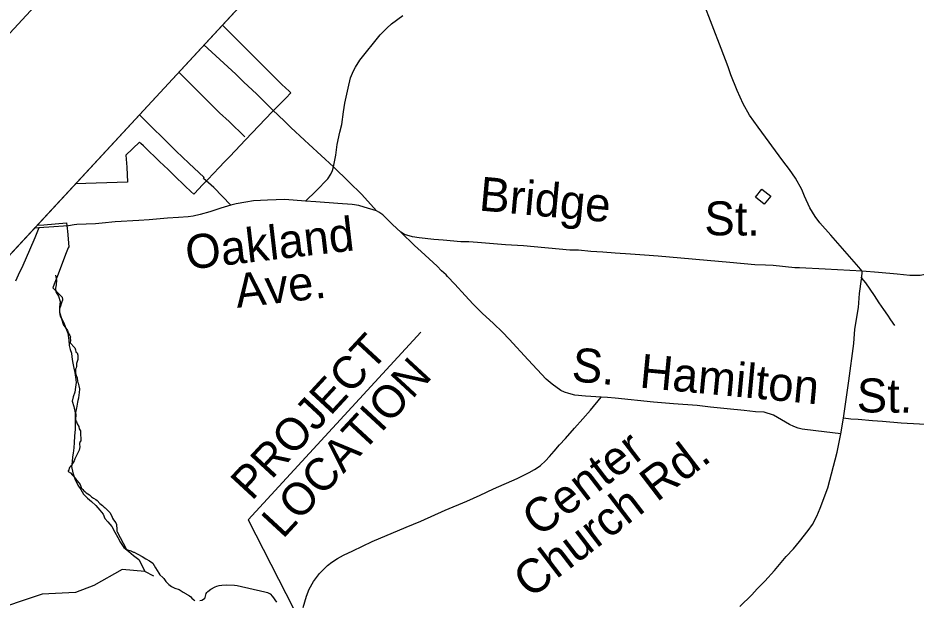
# Model space of a CAD drawing. Extents: x 1766669 to 1770980, y 998119 to 1002502.
# Drawn here: x 1767070.6 to 1767473.1, y 999839.2 to 1000100.2 of the extents above; entities that cross this region are included whole.
import ezdxf

# ---------------------------------------------------------------- set-up
doc = ezdxf.new("R2010")
doc.units = 0
for name, color, linetype in [('CTL Vertical Benchmark CELL', 7, 'Continuous'), ('Default', 7, 'Continuous'), ('Default Symbol CELL', 7, 'Continuous'), ('Exist DTM Breakline', 7, 'Continuous'), ('Exist DTM Breakline Underwater', 7, 'Continuous'), ('Exist Hydro Stream or Body of Water', 7, 'Continuous'), ('Exist Roads EOP', 7, 'Continuous'), ('Exist Structure Minor Pipes RCP 15 Inch', 7, 'Continuous'), ('Exist Structure Minor Pipes RCP 24 Inch', 7, 'Continuous')]:
    doc.layers.add(name, color=color, linetype=linetype)

msp = doc.modelspace()

# ---------------------------------------------------------------- linework, layer by layer
at = {"layer": 'CTL Vertical Benchmark CELL'}
for points in [[(1767448.78, 999983.55), (1767448.72, 999983.61), (1767448.45, 999983.95)], [(1767463.59, 999962.32), (1767461.83, 999964.83), (1767460.52, 999966.94), (1767458.7, 999969.51), (1767456.63, 999972.45), (1767454.43, 999975.75), (1767450.65, 999981.4), (1767448.78, 999983.55)]]:
    msp.add_lwpolyline(points, dxfattribs=at)
at = {"layer": 'Default'}
msp.add_lwpolyline([(1766911.45, 999825.82), (1767342.39, 1000292.03), (1767769.56, 999897.17), (1767338.62, 999430.96)], close=True, dxfattribs=at)
at = {"layer": 'Default Symbol CELL'}
for p, q in [((1769180.49, 1002379.93), (1766847.82, 999856.35)), ((1766911.45, 999825.82), (1767342.36, 1000292.01))]:
    msp.add_line(p, q, dxfattribs=at)
msp.add_lwpolyline([(1767251.23, 999959.27), (1767173.81, 999875.14), (1767194.02, 999835.43)], dxfattribs=at)
at = {"layer": 'Exist DTM Breakline'}
for p, q in [((1767079.99, 1000006.03), (1767077.93, 1000005.93)), ((1767448.78, 999983.55), (1767449.03, 999986.62)), ((1767439.43, 999913.72), (1767440.57, 999920.8))]:
    msp.add_line(p, q, dxfattribs=at)
for points in [[(1767449.03, 999986.62), (1767447.48, 999988.44), (1767434.84, 1000002.74), (1767430.04, 1000008.32), (1767427.83, 1000011.11), (1767425.5, 1000015.03), (1767423.11, 1000020.29), (1767421.99, 1000023.33), (1767419.11, 1000028.33), (1767416.37, 1000032.2), (1767413.4, 1000036.07), (1767402.41, 1000051.25), (1767398.48, 1000056.64), (1767395.65, 1000061.67), (1767392.91, 1000067.67), (1767390.15, 1000074.65), (1767388.94, 1000078.28), (1767385.7, 1000086.52), (1767377.73, 1000107.42)], [(1767212.01, 1000033.41), (1767213.09, 1000038.6), (1767213.69, 1000043.42), (1767214.89, 1000048.94), (1767215.69, 1000052.39), (1767216.47, 1000058.04), (1767217.14, 1000061.91), (1767218.53, 1000068.78), (1767219.69, 1000073.3), (1767221.05, 1000076.42), (1767221.91, 1000078.19), (1767223.75, 1000081.3), (1767232.93, 1000092.59), (1767235.92, 1000095.68), (1767237.94, 1000097.55), (1767243.03, 1000101.29)], [(1767212.01, 1000033.41), (1767200.97, 1000043.63), (1767198.95, 1000045.39), (1767192.95, 1000051.12), (1767190.11, 1000053.85), (1767184.62, 1000059.05), (1767184.5, 1000059.17), (1767177.49, 1000066.13), (1767171.81, 1000071.4), (1767168.2, 1000074.98), (1767153.97, 1000088.19)], [(1767142.63, 1000075.92), (1767160.93, 1000057.67), (1767165.28, 1000053.74), (1767172.35, 1000046.96)], [(1767166.06, 1000016.3), (1767158.42, 1000024.13), (1767153.74, 1000028.21), (1767154.13, 1000028.64), (1767147.13, 1000035.02), (1767141.46, 1000040.48), (1767124.98, 1000056.83)], [(1767199.51, 1000018.05), (1767204.24, 1000022.72), (1767209.44, 1000028.04), (1767210.86, 1000030.15), (1767211.53, 1000031.74), (1767212.01, 1000033.41)], [(1767231.36, 1000013.67), (1767224.71, 1000021.01), (1767218.84, 1000026.7), (1767212.01, 1000033.41)], [(1767199.51, 1000018.05), (1767190.2, 1000018.74), (1767182.41, 1000018.56), (1767176.24, 1000018.12), (1767172.72, 1000017.54), (1767168.46, 1000016.87), (1767166.06, 1000016.3)], [(1767166.06, 1000016.3), (1767161.5, 1000014.85), (1767156.53, 1000013.21), (1767152.23, 1000012.1), (1767149.07, 1000011.37), (1767146.89, 1000010.99), (1767142.56, 1000010.77), (1767137.59, 1000010.38), (1767129.43, 1000009.66), (1767124.75, 1000009.38), (1767114.15, 1000008.79), (1767108.27, 1000008.14), (1767105.36, 1000007.92), (1767096.94, 1000007.54), (1767095.75, 1000007.4), (1767093.22, 1000007.05), (1767084.51, 1000006.46), (1767079.99, 1000006.03)], [(1767231.36, 1000013.67), (1767225.82, 1000015.41), (1767223.36, 1000016.04), (1767220.42, 1000016.54), (1767213.95, 1000017.04), (1767204.06, 1000017.7), (1767199.51, 1000018.05)], [(1767242.19, 1000004.21), (1767240.36, 1000005.79), (1767238.34, 1000007.78), (1767234.06, 1000011.86), (1767232.37, 1000013.13), (1767231.36, 1000013.67)], [(1767079.99, 1000006.03), (1767078.17, 1000001.67), (1767075.75, 999996.04), (1767072.73, 999989.14), (1767070.65, 999984.82), (1767069.43, 999982.14)], [(1767449.03, 999986.62), (1767432.41, 999987.56), (1767420.86, 999988.17), (1767418.73, 999988.17), (1767409, 999989.16), (1767405.57, 999989.41), (1767400.85, 999989.49), (1767389.65, 999990.51), (1767357.6, 999993.38), (1767351.4, 999993.87), (1767345.1, 999994.26), (1767338.28, 999994.72), (1767332.71, 999995.24), (1767327.35, 999995.55), (1767321.78, 999996.07), (1767317.91, 999996.02), (1767297.2, 999998.04), (1767289.12, 999998.46), (1767276.51, 999999.44), (1767272.62, 999999.81), (1767269.06, 999999.88), (1767261.19, 1000000.53), (1767256.99, 1000000.8), (1767250.39, 1000001.64), (1767247.4, 1000002.07), (1767243.81, 1000003.17), (1767242.19, 1000004.21)], [(1767331.92, 999930.19), (1767325.01, 999930.56), (1767320.23, 999931.11), (1767317.47, 999931.85), (1767315.49, 999932.37), (1767313.9, 999933.2), (1767310.02, 999935.99), (1767307.32, 999938.3), (1767299.33, 999946.87), (1767290.79, 999956.2), (1767287.77, 999959.34), (1767283.73, 999963.17), (1767278.66, 999967.86), (1767274.56, 999971.89), (1767271.03, 999975.8), (1767266.44, 999980.76), (1767263.1, 999984.25), (1767262.56, 999984.95), (1767260.49, 999986.87), (1767258.47, 999988.84), (1767251.32, 999995.54), (1767248.29, 999998.11), (1767242.19, 1000004.21)], [(1767440.57, 999920.8), (1767442.93, 999937.5), (1767445.2, 999954.24), (1767445.7, 999960.7), (1767447.27, 999970.36), (1767447.78, 999976.7), (1767448.69, 999983.06), (1767448.78, 999983.55)], [(1767198.42, 999835.93), (1767199.89, 999841.01), (1767201.18, 999844.05), (1767202.99, 999847.53), (1767205.68, 999851.17), (1767209.35, 999854.69), (1767211.32, 999856.14), (1767213.83, 999857.8), (1767216.46, 999859.34), (1767220.67, 999861.33), (1767229.37, 999865.46), (1767244.57, 999871.85), (1767251.21, 999874.64), (1767262.13, 999879.43), (1767271.8, 999883.53), (1767277.72, 999886.23), (1767283.78, 999889.04), (1767294.33, 999893.77), (1767299.77, 999896.4), (1767302.16, 999897.67), (1767303.33, 999898.54), (1767304.74, 999899.58), (1767307, 999901.66), (1767308.82, 999903.62), (1767310.96, 999905.94), (1767313.26, 999908.82), (1767315.97, 999911.68), (1767320.03, 999916.22), (1767323.71, 999920.47), (1767327.15, 999924.34), (1767331.92, 999930.19)], [(1767439.43, 999913.72), (1767428.19, 999915), (1767422.13, 999915.85), (1767420.24, 999916.21), (1767418.26, 999917), (1767416.36, 999917.95), (1767409.15, 999922.13), (1767405.1, 999923.37), (1767401.13, 999923.53), (1767396.07, 999924.26), (1767388.49, 999924.92), (1767380.98, 999925.7), (1767375.06, 999926.36), (1767364.47, 999927.23), (1767355.37, 999928), (1767338.24, 999929.75), (1767334.82, 999929.96), (1767331.92, 999930.19)], [(1767512.56, 999916.78), (1767507.18, 999917.1), (1767502.85, 999917.55), (1767499.63, 999917.94), (1767495.74, 999918.17), (1767492.81, 999918.36), (1767489.89, 999918.34), (1767482.03, 999917.75), (1767474.65, 999918.11), (1767466.43, 999918.58), (1767458.13, 999919.31), (1767453.55, 999919.51), (1767447.21, 999920.15), (1767443.86, 999920.35), (1767440.57, 999920.8)], [(1767394.09, 999836.38), (1767399.58, 999841.6), (1767401.84, 999844.18), (1767405.26, 999847.7), (1767409.65, 999852.46), (1767414.96, 999858.67), (1767418.13, 999862.11), (1767420.82, 999865.45), (1767424.78, 999870.45), (1767426.63, 999873.08), (1767428.62, 999876.87), (1767430.2, 999880.39), (1767433.63, 999889.57), (1767437.69, 999905.55), (1767439.43, 999913.72)]]:
    msp.add_lwpolyline(points, dxfattribs=at)
at = {"layer": 'Exist DTM Breakline Underwater'}
msp.add_lwpolyline([(1767546.9, 1000094.09), (1767543.97, 1000089.39), (1767543.53, 1000088.68), (1767539.35, 1000082.48), (1767527.82, 1000062.47), (1767521.46, 1000052.31), (1767512.44, 1000038.59), (1767508.74, 1000032.63), (1767496.39, 1000011.99), (1767484.78, 999993.13), (1767480.48, 999987.65), (1767479.64, 999986.62), (1767477.21, 999985.17), (1767474.96, 999984.72), (1767470.32, 999984.72), (1767464.69, 999985.28), (1767456.33, 999986.13), (1767449.03, 999986.62)], dxfattribs=at)
at = {"layer": 'Exist Hydro Stream or Body of Water'}
msp.add_lwpolyline([(1767162.14, 1000097.04), (1767188.91, 1000070.4), (1767192.11, 1000067.35), (1767192.84, 1000066.64), (1767190.59, 1000064.29), (1767184.59, 1000058.04), (1767172.64, 1000045.57), (1767167.9, 1000040.6), (1767165.54, 1000038.11), (1767163.17, 1000035.64), (1767160.76, 1000033.1), (1767155.7, 1000027.8), (1767154.51, 1000026.56), (1767153.04, 1000025.03), (1767151.81, 1000023.75), (1767149.36, 1000021.18), (1767148.09, 1000022.34), (1767145.6, 1000024.75), (1767140.65, 1000029.54), (1767138.16, 1000031.93), (1767135.66, 1000034.35), (1767134.38, 1000035.58), (1767131.93, 1000037.95), (1767129.45, 1000040.34), (1767127.52, 1000042.22), (1767126.91, 1000042.8), (1767125.73, 1000043.93), (1767125.12, 1000044.51), (1767118.96, 1000038.67), (1767119.33, 1000033.36), (1767119.77, 1000026.61), (1767096.38, 1000025.89)], dxfattribs=at)
at = {"layer": 'Exist Roads EOP'}
msp.add_line((1767131.54, 999849.96), (1767127.45, 999852.04), dxfattribs=at)
for points in [[(1767087.4, 999984.82), (1767087.93, 999982.59), (1767087.78, 999980.51), (1767087.41, 999979.09), (1767087.55, 999977.45), (1767088.79, 999975.49), (1767089.45, 999973.02), (1767089.25, 999970.51), (1767089.28, 999968.26), (1767090.08, 999965.43), (1767091.09, 999963.46), (1767092.1, 999961.13), (1767092.93, 999958.84), (1767093.37, 999955.76), (1767093.48, 999953.32), (1767094.05, 999951.52), (1767094.66, 999949.9), (1767094.8, 999948.26), (1767095.01, 999946.2), (1767095.69, 999943.24), (1767096.14, 999941.18), (1767096.42, 999939.07), (1767096.64, 999936.76), (1767096.43, 999934.62), (1767096.04, 999932.41), (1767095.4, 999930.31), (1767094.93, 999928.39), (1767095.71, 999925.93), (1767096.2, 999923.15), (1767096.3, 999920.84), (1767096.18, 999918.03), (1767096.22, 999915.77), (1767095.99, 999912.72), (1767095.81, 999909.85), (1767095.66, 999907.52), (1767095.4, 999905.08), (1767095.11, 999903.48), (1767094.84, 999901.15), (1767094.63, 999899.01), (1767095.18, 999896.29), (1767096.03, 999893.52), (1767097.37, 999890.66), (1767098.74, 999888.7), (1767100.05, 999886.68), (1767101.83, 999884.81), (1767103.54, 999883.36), (1767105.51, 999881.67), (1767107.31, 999879.55), (1767108.73, 999877.66), (1767109.6, 999875.81), (1767110.83, 999874.22), (1767112.69, 999872.16), (1767113.96, 999869.6), (1767115.29, 999867.22), (1767116.54, 999865.01), (1767118.1, 999862.76), (1767120.25, 999861.02), (1767122.4, 999859.16), (1767124.8, 999857.44), (1767126.37, 999854.31), (1767127.45, 999852.04)], [(1767127.45, 999852.04), (1767117.35, 999852.94), (1767104.67, 999845.68), (1767096.41, 999842.6), (1767081.44, 999841.91), (1767056.77, 999833.6), (1767028.19, 999831.39), (1767010.54, 999827.31)]]:
    msp.add_lwpolyline(points, dxfattribs=at)
at = {"layer": 'Exist Structure Minor Pipes RCP 15 Inch'}
msp.add_lwpolyline([(1767405.1, 1000016.77), (1767401.17, 1000019.88), (1767404.01, 1000023.47), (1767407.95, 1000020.36)], close=True, dxfattribs=at)
at = {"layer": 'Exist Structure Minor Pipes RCP 24 Inch'}
for points in [[(1767079.17, 1000007.27), (1767082.24, 1000007.5), (1767092.29, 1000008.31), (1767092.68, 1000005.79), (1767092.76, 1000004.61), (1767093.39, 999997.64), (1767093.16, 999997.14), (1767091.92, 999994.06), (1767088.55, 999985.37), (1767086.81, 999980.88), (1767086.16, 999979.25), (1767090.09, 999975.34), (1767090.38, 999975.06), (1767090.51, 999974.01), (1767090.49, 999973.69), (1767090.28, 999972.92), (1767089.92, 999971.97), (1767089.64, 999970.83), (1767089.38, 999970.28), (1767089.24, 999969.76), (1767089.2, 999968.31), (1767089.37, 999967.13), (1767089.55, 999966.46), (1767090.07, 999965.25), (1767091.08, 999962.45), (1767091.26, 999962.18), (1767092.77, 999960.02), (1767092.98, 999959.57), (1767093.05, 999959.01), (1767093.85, 999957.82), (1767094.08, 999957.27), (1767094.03, 999956.7), (1767094.12, 999955.63), (1767094.03, 999954.62), (1767094.2, 999954.34), (1767095.8, 999952.66), (1767096.05, 999952.25), (1767096.38, 999951.39), (1767096.55, 999950.51), (1767096.66, 999950.33), (1767097.15, 999949.97), (1767097.31, 999949.62), (1767097.36, 999949.49), (1767097.48, 999949.02), (1767097.5, 999948.46), (1767097.38, 999947.01), (1767097.31, 999946.54), (1767096.88, 999945.29), (1767096.77, 999943.98), (1767096.63, 999943.37), (1767096.46, 999942.79), (1767096.38, 999941.97), (1767096.45, 999940.88), (1767096.68, 999939.88), (1767097.08, 999938.8), (1767097.34, 999937.41), (1767097.51, 999936.79), (1767097.6, 999936.46), (1767097.91, 999935.21), (1767098.13, 999933.91), (1767097.99, 999932.12), (1767097.95, 999931.27), (1767097.71, 999929.67), (1767097.41, 999928.61), (1767097.3, 999928), (1767096.8, 999925.18), (1767096.69, 999924.86), (1767096.58, 999923.76), (1767096.44, 999923.38), (1767096.43, 999923.35), (1767096.54, 999922.28), (1767096.36, 999920.18), (1767096.55, 999919.59), (1767096.8, 999919.16), (1767097.2, 999918.2), (1767097.81, 999917.03), (1767098.06, 999915.91), (1767098.56, 999915.09), (1767098.68, 999914.55), (1767098.77, 999910.56), (1767098.77, 999910.51), (1767098.66, 999910.36), (1767098.49, 999910.28), (1767098.47, 999910.24), (1767098.21, 999909.45), (1767098.16, 999909.09), (1767098.36, 999907.88), (1767098.02, 999906.34), (1767097.18, 999904.54), (1767096.7, 999903.77), (1767096.09, 999902.48), (1767095.8, 999901.69), (1767095.35, 999900.87), (1767094.98, 999900.46), (1767094.82, 999900), (1767094.73, 999899.53), (1767094.1, 999899.08), (1767093.76, 999898.68), (1767093.52, 999898.13), (1767093.43, 999897.57), (1767093.11, 999897.17), (1767093.1, 999897), (1767093.16, 999896.86), (1767094.13, 999896.21), (1767094.83, 999895.36), (1767095.37, 999894.91), (1767096.37, 999893.72), (1767096.46, 999893.62), (1767098.44, 999891.03), (1767098.68, 999890.54), (1767098.93, 999889.62), (1767099.08, 999889.35), (1767099.64, 999888.78), (1767100.07, 999888.19), (1767100.59, 999887.84), (1767101.21, 999887.25), (1767102.65, 999886.33), (1767103.52, 999885.42), (1767104.4, 999884.83), (1767105.47, 999884.25), (1767106.06, 999883.78), (1767107.3, 999882.5), (1767108.44, 999881.65), (1767109.17, 999880.91), (1767109.73, 999880.49), (1767110.36, 999879.8), (1767111.38, 999878.93), (1767111.73, 999878.48), (1767112.67, 999876.81), (1767113, 999875.97), (1767113.39, 999875.24), (1767114.42, 999873.84), (1767114.72, 999873.01), (1767114.77, 999872.61), (1767114.9, 999871.28), (1767114.89, 999870.12), (1767115.03, 999869.85), (1767119.08, 999862.15), (1767119.33, 999861.92), (1767119.72, 999861.72), (1767121.19, 999861.23), (1767122.35, 999860.7), (1767122.67, 999860.62), (1767123.72, 999860.09), (1767124.27, 999859.73), (1767126.2, 999858.79), (1767127.91, 999857.64), (1767129.61, 999856.76), (1767131.09, 999855.81), (1767132.18, 999853.6), (1767133.67, 999851.25), (1767134.24, 999850.53), (1767135.51, 999849.31), (1767135.95, 999848.81), (1767136.94, 999847.45), (1767138.16, 999846.16), (1767139.41, 999845.22), (1767140.88, 999844.57), (1767142.79, 999843.87), (1767144.66, 999842.81), (1767145.99, 999842.02), (1767146.2, 999841.9), (1767147.42, 999841.14), (1767148.04, 999840.59), (1767148.5, 999840.06), (1767149.4, 999839.29), (1767149.93, 999839.04)], [(1767152.07, 999839.01), (1767153.05, 999839.21), (1767153.78, 999839.58), (1767154.3, 999840.07), (1767154.46, 999840.36), (1767155.01, 999842.13), (1767155.29, 999842.6), (1767155.65, 999843.01), (1767157.11, 999844.06), (1767159.05, 999845.13), (1767159.75, 999845.43), (1767160.8, 999845.72), (1767161.93, 999845.92), (1767164, 999846.05), (1767167.64, 999845.91), (1767168.78, 999845.71), (1767181.32, 999842.82), (1767182.37, 999842.53), (1767183.68, 999842.04), (1767184.73, 999840.8), (1767186.45, 999838.27)]]:
    msp.add_lwpolyline(points, dxfattribs=at)

# ---------------------------------------------------------------- texts
at = {"layer": 'Default Symbol CELL'}
for s, height, rotation, p in [('Bridge', 15.235, 354.7807, (1767276.91, 1000013.9)), ('St.', 15.235, 359.6622, (1767378.23, 1000002.76)), ('Oakland', 15.235, 6.6113, (1767146.55, 999987.31)), (' Ave.', 15.235, 6.6113, (1767163.19, 999969.53)), ('PROJECT ', 14.54, 47.2512, (1767175.42, 999883.38)), ('S.  Hamilton', 15.2352, 354.5993, (1767318.42, 999937.38)), ('LOCATION', 14.54, 47.2512, (1767189.31, 999866.28)), ('St.', 15.235, 359.4808, (1767446.51, 999923.38)), ('Church Rd.', 15.235, 37.4132, (1767300.23, 999839.51)), ('Center ', 15.235, 37.4132, (1767304.06, 999867.08))]:
    msp.add_text(s, height=height, rotation=rotation, dxfattribs=at).set_placement(p)

doc.saveas('drawing.dxf')
